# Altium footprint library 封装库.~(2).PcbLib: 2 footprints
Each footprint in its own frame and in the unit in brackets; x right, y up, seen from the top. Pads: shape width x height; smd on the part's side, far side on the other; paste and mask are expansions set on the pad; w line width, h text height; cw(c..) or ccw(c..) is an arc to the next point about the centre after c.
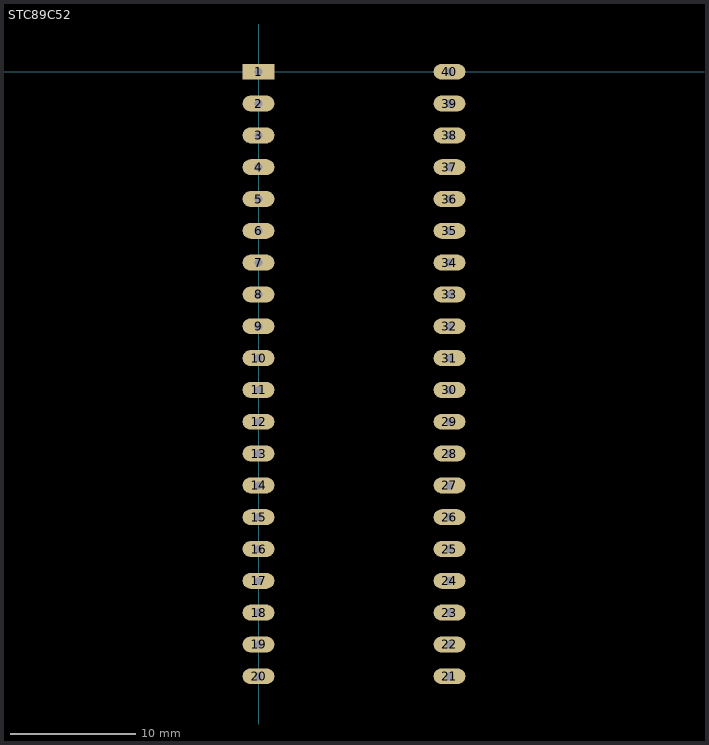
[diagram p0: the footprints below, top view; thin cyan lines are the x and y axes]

## PCBComponent_1 [mil]

## STC89C52 [mil]
pads (40):
  rect 100x50 hole 25: 1(0,0)
  oval 100x50 hole 25: 2(0,-100) 3(0,-200) 4(0,-300) 5(0,-400) 6(0,-500) 7(0,-600) 8(0,-700) 9(0,-800) 10(0,-900) 11(0,-1000) 12(0,-1100) 13(0,-1200) 14(0,-1300) 15(0,-1400) 16(0,-1500) 17(0,-1600) 18(0,-1700) 19(0,-1800) 20(0,-1900) 21(600,-1900) 22(600,-1800) 23(600,-1700) 24(600,-1600) 25(600,-1500) 26(600,-1400) 27(600,-1300) 28(600,-1200) 29(600,-1100) 30(600,-1000) 31(600,-900) 32(600,-800) 33(600,-700) 34(600,-600) 35(600,-500) 36(600,-400) 37(600,-300) 38(600,-200) 39(600,-100) 40(600,0)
